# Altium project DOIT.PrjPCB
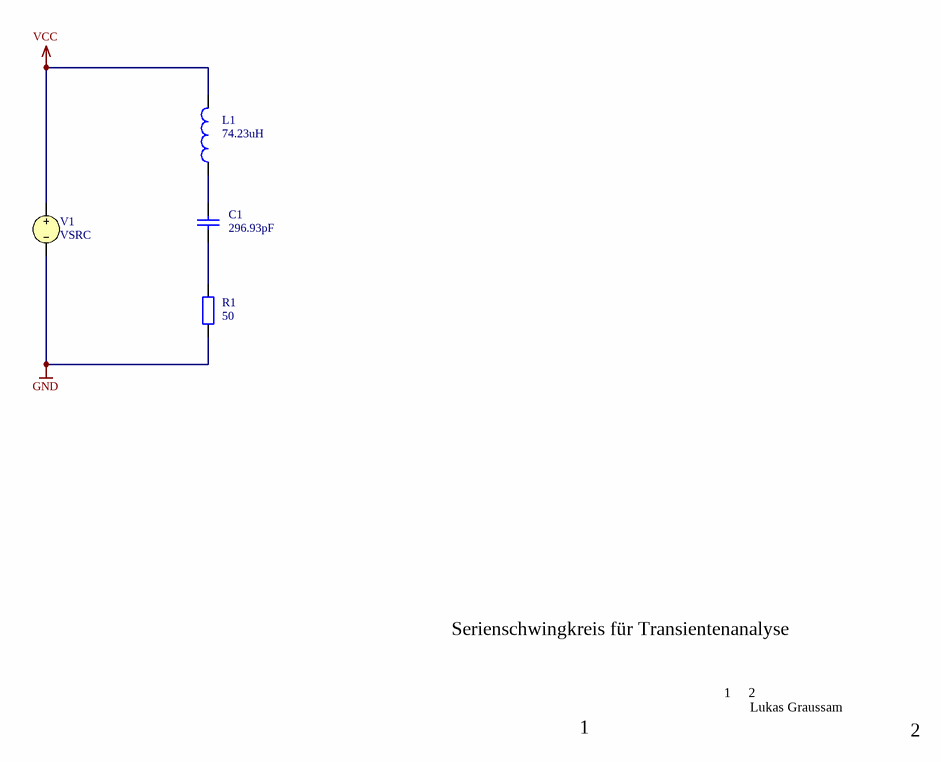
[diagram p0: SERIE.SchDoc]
2 sheets, 8 parts. Net scope: global (net labels, ports and power ports of the same name join across sheets).
Sheets:
  SERIE.SchDoc
  Serie_AC.SchDoc

## Sheet SERIE.SchDoc
size A4; PageSetup: Record=PageOptions¦CenterHorizontal=True¦CenterVertical=True¦PrintScale=1.00¦XCorrection=1.00¦YCorrection=1.00¦PrintKind=0¦BorderSize=5000000¦LeftOffset=0¦BottomOffset=0¦Orientation=2¦PaperLength=1000¦PaperWidth=1000¦Scale=100¦PaperSource=7¦PrintQuality=-3¦MediaType=1¦DitherType=10¦PrintScaleMode=1¦PaperKind=A4¦PaperIndex=9

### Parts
C1  value 296.93pF  [RAD-0.3]  (hidden comment: Cap)
L1  value 74.23uH  [0402-A]  (hidden comment: Inductor)
R1  value 50  [AXIAL-0.4]  (hidden comment: Res2)
V1  VSRC

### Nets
GND: R1.1 V1.2
VCC: L1.2 V1.1
NetC1_1: C1.1 L1.1
NetC1_2: C1.2 R1.2

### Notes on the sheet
- Serienschwingkreis für Transientenanalyse
- 1
- 2
- Lukas Graussam

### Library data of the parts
C1 = Cap: Capacitor
L1 = Inductor: Code_IEC: 1005
R1 = Res2: Resistor
V1 = VSRC: Voltage Source; Note: PCB Footprint - Not required; Value: 10mV

## Sheet Serie_AC.SchDoc
size A4; PageSetup: Record=PageOptions¦CenterHorizontal=True¦CenterVertical=True¦PrintScale=1.00¦XCorrection=1.00¦YCorrection=1.00¦PrintKind=0¦BorderSize=5000000¦LeftOffset=0¦BottomOffset=0¦Orientation=2¦PaperLength=1000¦PaperWidth=1000¦Scale=100¦PaperSource=7¦PrintQuality=-3¦MediaType=1¦DitherType=10¦PrintScaleMode=1¦PaperKind=A4¦PaperIndex=9
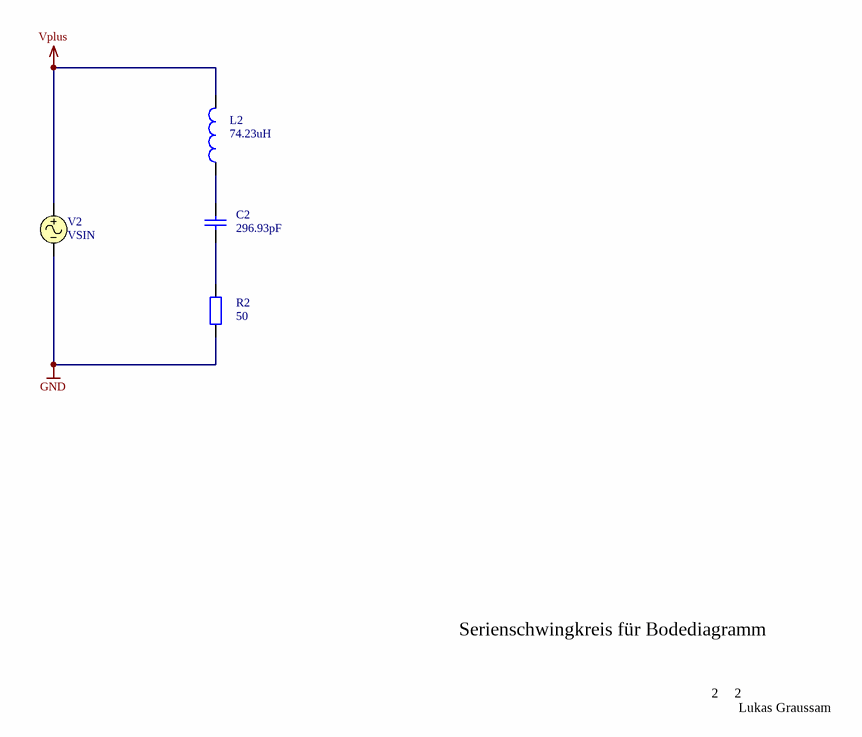
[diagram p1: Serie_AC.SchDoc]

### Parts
C2  value 296.93pF  [RAD-0.3]  (hidden comment: Cap)
L2  value 74.23uH  [0402-A]  (hidden comment: Inductor)
R2  value 50  [AXIAL-0.4]  (hidden comment: Res2)
V2  VSIN

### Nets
GND: R2.1 V2.2
Vplus: L2.2 V2.1
NetC2_1: C2.1 L2.1
NetC2_2: C2.2 R2.2

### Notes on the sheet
- Serienschwingkreis für Bodediagramm
- 2
- Lukas Graussam

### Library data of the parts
C2 = Cap: Capacitor
L2 = Inductor: Code_IEC: 1005
R2 = Res2: Resistor
V2 = VSIN: Sinusoidal Voltage Source; Note: PCB Footprint - Not required

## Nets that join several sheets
GND: SERIE (R1.1 V1.2), Serie_AC (R2.1 V2.2)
